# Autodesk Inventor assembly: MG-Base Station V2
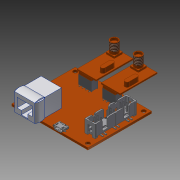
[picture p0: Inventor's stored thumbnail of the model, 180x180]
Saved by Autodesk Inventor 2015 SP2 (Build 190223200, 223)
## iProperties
Created: 2014-11
Part Number: MG-Base Station V2
Document SubType Name: Assembly
Designer: rYan
Author: rYan
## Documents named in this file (7)
- E:\Tigers SVN\mechanik\2016\Inventor\Elektronik\MG-Base Station V2.iam
- E:\Tigers SVN\mechanik\2016\Inventor\Elektronik\Base Station V2.ipt
- E:\Tigers SVN\mechanik\2016\Inventor\Kaufteile\RJ45 Socket.ipt
- E:\Tigers SVN\mechanik\2016\Inventor\Kaufteile\N2520-6V0C-RB-WE.ipt
- E:\Tigers SVN\mechanik\2016\Inventor\Kaufteile\SSM-104-L-DV.ipt
- E:\Tigers SVN\mechanik\2016\Inventor\Kaufteile\Micro-USB.ipt
- E:\Tigers SVN\mechanik\2016\Inventor\Kaufteile\NRF24L01 SMA.ipt
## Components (8 placed, 6 different names)
1. Base Station V2:1 — Passend:1, Passend:2, Passend:3, Passend:4, Fluchtend:1, Fluchtend:2, Passend:5, Passend:6, Passend:7, Fluchtend:3, Fluchtend:4, Fluchtend:5, Fluchtend:7
2. RJ45 Socket:1 — Passend:1, Passend:2, Passend:3
3. N2520-6V0C-RB-WE:1 — Passend:5, Fluchtend:3, Fluchtend:4
4. SSM-104-L-DV:1 — Passend:7, Fluchtend:6, Fluchtend:7, Passend:8, Passend:9, Fluchtend:9, Fluchtend:10
5. SSM-104-L-DV:2 — Passend:6, Fluchtend:5, Fluchtend:6, Passend:8, Passend:10, Fluchtend:8, Fluchtend:11
6. Micro-USB 47346-0001:1 — Passend:4, Fluchtend:1, Fluchtend:2
7. NRF24L01 SMA:1 — Passend:9, Fluchtend:9, Fluchtend:10
8. NRF24L01 SMA:2 — Passend:10, Fluchtend:8, Fluchtend:11
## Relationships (21: Flush 11, Mate 10)
- Passend:1 [Mate]: Base Station V2:1 ↔ RJ45 Socket:1
- Passend:2 [Mate]: Base Station V2:1 ↔ RJ45 Socket:1
- Passend:3 [Mate]: Base Station V2:1 ↔ RJ45 Socket:1
- Passend:4 [Mate]: Base Station V2:1 ↔ Micro-USB 47346-0001:1
- Fluchtend:1 [Flush]: Base Station V2:1 ↔ Micro-USB 47346-0001:1
- Fluchtend:2 [Flush]: Base Station V2:1 ↔ Micro-USB 47346-0001:1
- Passend:5 [Mate]: Base Station V2:1 ↔ N2520-6V0C-RB-WE:1
- Passend:6 [Mate]: Base Station V2:1 ↔ SSM-104-L-DV:2
- Passend:7 [Mate]: Base Station V2:1 ↔ SSM-104-L-DV:1
- Fluchtend:3 [Flush]: Base Station V2:1 ↔ N2520-6V0C-RB-WE:1
- Fluchtend:4 [Flush]: Base Station V2:1 ↔ N2520-6V0C-RB-WE:1
- Fluchtend:5 [Flush]: Base Station V2:1 ↔ SSM-104-L-DV:2
- Fluchtend:6 [Flush]: SSM-104-L-DV:1 ↔ SSM-104-L-DV:2
- Fluchtend:7 [Flush]: Base Station V2:1 ↔ SSM-104-L-DV:1
- Passend:8 [Mate]: SSM-104-L-DV:1 ↔ SSM-104-L-DV:2
- Passend:9 [Mate]: SSM-104-L-DV:1 ↔ NRF24L01 SMA:1
- Passend:10 [Mate]: SSM-104-L-DV:2 ↔ NRF24L01 SMA:2
- Fluchtend:8 [Flush]: SSM-104-L-DV:2 ↔ NRF24L01 SMA:2
- Fluchtend:9 [Flush]: SSM-104-L-DV:1 ↔ NRF24L01 SMA:1
- Fluchtend:10 [Flush]: SSM-104-L-DV:1 ↔ NRF24L01 SMA:1
- Fluchtend:11 [Flush]: SSM-104-L-DV:2 ↔ NRF24L01 SMA:2
